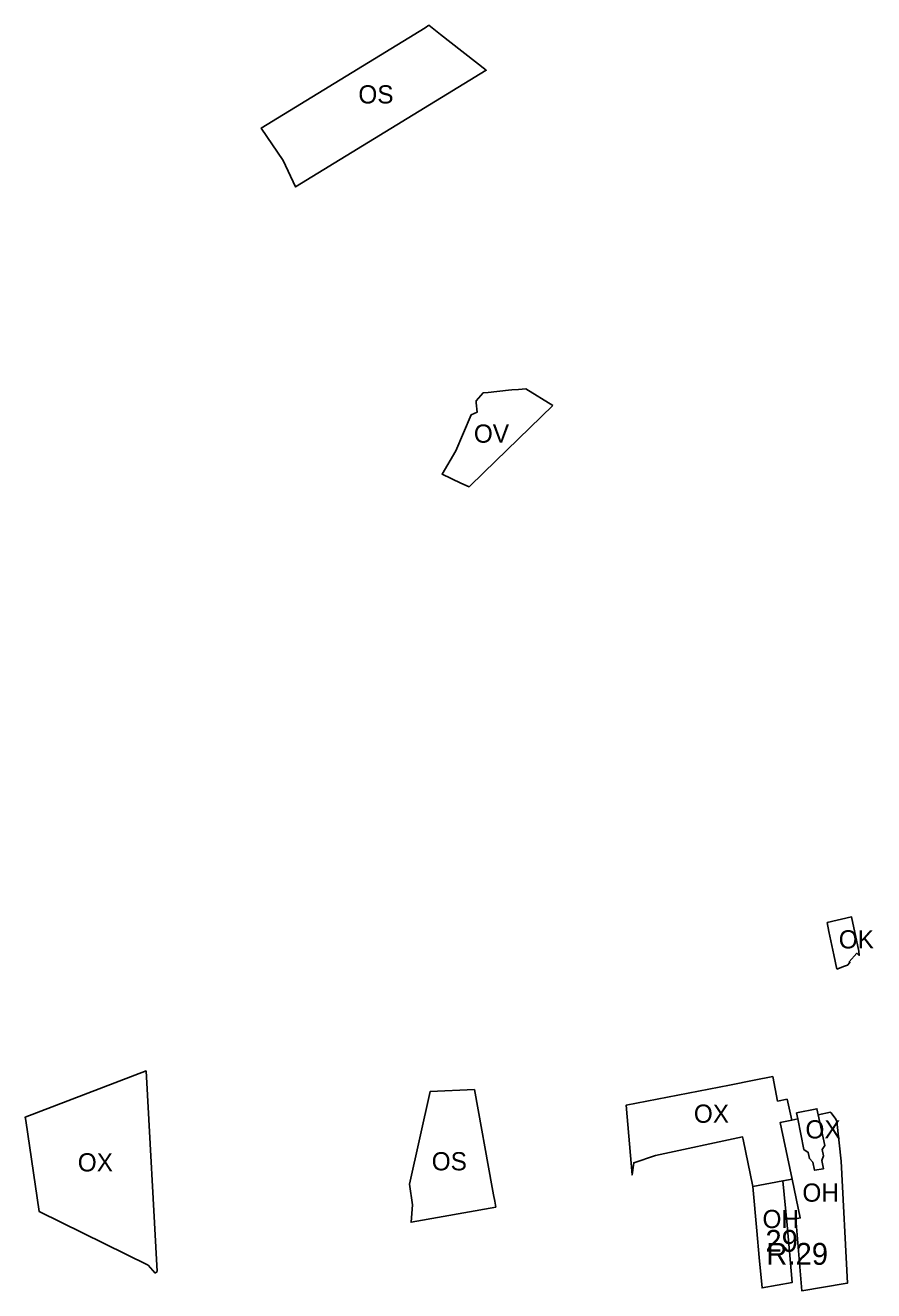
# Model space of a CAD drawing. Extents: x -520747 to -519277, y -1141727 to -1140602.
import ezdxf

# ---------------------------------------------------------------- set-up
doc = ezdxf.new("R2010")
doc.units = 0
for name, color, linetype in [('90210033', 7, 'Continuous'), ('90220013', 7, 'Continuous'), ('90660013', 7, 'Continuous'), ('90670013', 7, 'Continuous'), ('90680023', 7, 'Continuous'), ('90710013', 7, 'Continuous'), ('ID_navrh', 7, 'Continuous'), ('ID_rezervaR', 7, 'Continuous')]:
    doc.layers.add(name, color=color, linetype=linetype)

msp = doc.modelspace()

# ---------------------------------------------------------------- linework, layer by layer
at = {"layer": '90210033'}
msp.add_lwpolyline([(-520328.39, -1141261.02), (-520330.62, -1141236.74), (-520347.19, -1141239.81), (-520344.95, -1141264.09), (-520343.6, -1141278.76), (-520342.05, -1141295.55), (-520325.5, -1141292.44), (-520327.05, -1141275.53)], close=True, dxfattribs=at)
at = {"layer": '90220013'}
msp.add_lwpolyline([(-520300.97, -1141120.47), (-520296.78, -1141118.85), (-520295.14, -1141118.22), (-520293.88, -1141116.78), (-520294.23, -1141116.47), (-520290.03, -1141111.68), (-520288.75, -1141112.92), (-520289, -1141110.56), (-520292.97, -1141091.81), (-520306.28, -1141094.87), (-520305.34, -1141099.75), (-520302.64, -1141112.56), (-520300.97, -1141120.47)], dxfattribs=at)
at = {"layer": '90660013'}
msp.add_lwpolyline([(-520456.93, -1140810.9), (-520471.87, -1140801.78), (-520475.9, -1140802.08), (-520479.52, -1140802.35), (-520481.31, -1140802.54), (-520492.42, -1140803.71), (-520495.25, -1140804.01), (-520499.12, -1140808.43), (-520499.02, -1140809.41), (-520498.5, -1140814.52), (-520501.75, -1140815.97), (-520510.31, -1140835.9), (-520517.77, -1140848.71), (-520507.49, -1140853.67), (-520502.85, -1140855.53), (-520494.89, -1140847.8), (-520456.93, -1140810.9)], dxfattribs=at)
at = {"layer": '90670013'}
msp.add_lwpolyline([(-520325.59, -1141235.8), (-520321.16, -1141257.11), (-520323.62, -1141257.49), (-520320.29, -1141297.03), (-520296.48, -1141293.05), (-520295.11, -1141292.82), (-520298.61, -1141225.85), (-520300.95, -1141204.15), (-520301.55, -1141202.8), (-520304.21, -1141199.32), (-520304.49, -1141199.02), (-520311.28, -1141200.4), (-520307.6, -1141217.21), (-520309.05, -1141219.45), (-520308.34, -1141222.91), (-520309.23, -1141225.55), (-520308.37, -1141230.04), (-520313.3, -1141230.91), (-520314.28, -1141226.51), (-520316.06, -1141224.47), (-520316.76, -1141221.12), (-520319.07, -1141219.54), (-520322.39, -1141202.63), (-520325.76, -1141203.31), (-520332.09, -1141204.58), (-520331.36, -1141208.07), (-520325.59, -1141235.8)], dxfattribs=at)
at = {"layer": '90710013'}
for points in [[(-520525.02, -1140602.15), (-520527.15, -1140603.46), (-520617.05, -1140658.61), (-520605.12, -1140676.44), (-520598.21, -1140690.89), (-520493.55, -1140626.8), (-520518.65, -1140607.14), (-520525.02, -1140602.15)], [(-520488.89, -1141247.94), (-520489.54, -1141244.37), (-520490.28, -1141240.29), (-520500.08, -1141186.63), (-520524.27, -1141187.6), (-520535.7, -1141238.47), (-520534.05, -1141249.88), (-520534.84, -1141259.42), (-520488.31, -1141251.1), (-520488.89, -1141247.94)]]:
    msp.add_lwpolyline(points, dxfattribs=at)
at = {"layer": 'ID_navrh'}
for points in [[(-520675.31, -1141287.41), (-520674.18, -1141286.49), (-520680.34, -1141176.38), (-520746.65, -1141201.66), (-520746.38, -1141203.48), (-520739.03, -1141253.62), (-520679.28, -1141282.96), (-520675.31, -1141287.41)], [(-520325.59, -1141235.8), (-520331.36, -1141208.07), (-520332.09, -1141204.58), (-520325.76, -1141203.31), (-520328.4, -1141191.92), (-520333.6, -1141192.88), (-520336.24, -1141179.42), (-520346.46, -1141181.44), (-520359.99, -1141184.11), (-520416.76, -1141195.21), (-520413.51, -1141233.43), (-520412.54, -1141226.76), (-520400.61, -1141222.82), (-520352.78, -1141212.63), (-520352.51, -1141213.97), (-520352.46, -1141213.96), (-520347.19, -1141239.81), (-520330.62, -1141236.74), (-520325.59, -1141235.8)], [(-520311.28, -1141200.4), (-520312, -1141197.1), (-520323.1, -1141199.37), (-520322.39, -1141202.63), (-520319.07, -1141219.54), (-520316.76, -1141221.12), (-520316.06, -1141224.47), (-520314.28, -1141226.51), (-520313.3, -1141230.91), (-520308.37, -1141230.04), (-520309.23, -1141225.55), (-520308.34, -1141222.91), (-520309.05, -1141219.45), (-520307.6, -1141217.21), (-520311.28, -1141200.4)]]:
    msp.add_lwpolyline(points, dxfattribs=at)

# ---------------------------------------------------------------- texts
at = {"layer": '90210033'}
msp.add_text('OH', height=10, rotation=0, dxfattribs=at).set_placement((-520341.86, -1141262.65))
at = {"layer": '90220013'}
msp.add_text('OK', height=10, rotation=0, dxfattribs=at).set_placement((-520299.97, -1141109.08))
at = {"layer": '90660013'}
msp.add_text('OV', height=10, rotation=360, dxfattribs=at).set_placement((-520500.35, -1140831.36))
at = {"layer": '90670013'}
msp.add_text('OH', height=10, rotation=360, dxfattribs=at).set_placement((-520319.95, -1141248.16))
at = {"layer": '90680023'}
msp.add_text('29', height=12, rotation=0, dxfattribs=at).set_placement((-520340.26, -1141275.66))
at = {"layer": '90710013'}
for p in [(-520563.78, -1140645.07), (-520523.49, -1141230.96)]:
    msp.add_text('OS', height=10, rotation=360, dxfattribs=at).set_placement(p)
at = {"layer": 'ID_navrh'}
for rotation, p in [(0, (-520379.56, -1141204.82)), (0, (-520318.27, -1141213.43)), (360, (-520717.84, -1141231.54))]:
    msp.add_text('OX', height=10, rotation=rotation, dxfattribs=at).set_placement(p)
at = {"layer": 'ID_rezervaR'}
msp.add_text('R.29', height=12, rotation=0, dxfattribs=at).set_placement((-520339.76, -1141282.81))

doc.saveas('drawing.dxf')
